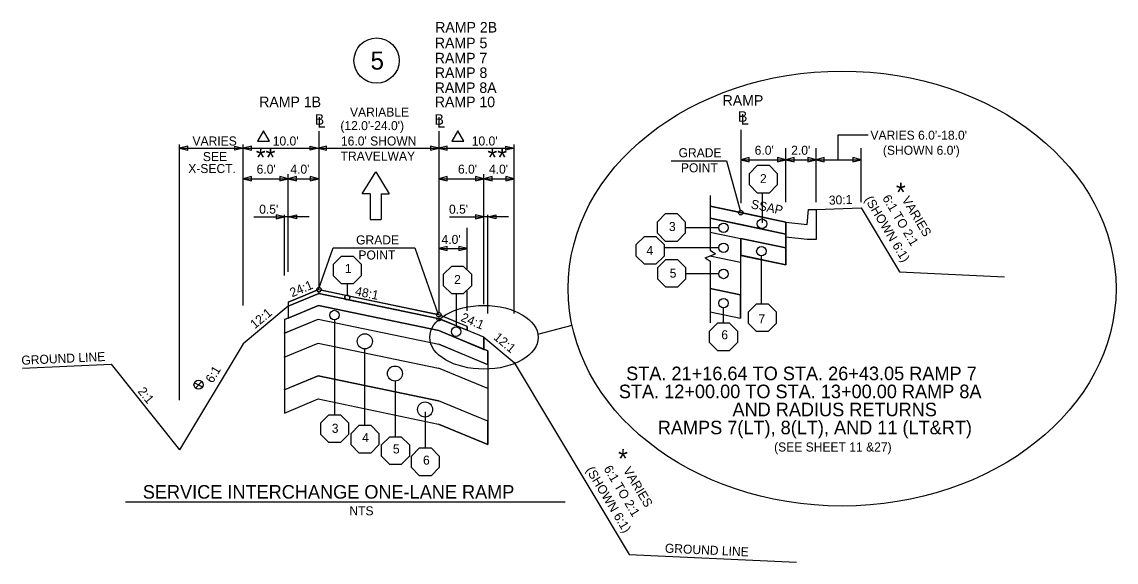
# Model space of a CAD drawing. Extents: x 4649 to 5578, y 4853 to 5383.
# Drawn here: x 4648.7 to 4794, y 5061.2 to 5132.9 of the extents above; entities that cross this region are included whole.
import ezdxf

# ---------------------------------------------------------------- set-up
doc = ezdxf.new("R2010")
doc.units = 0
for name, color, linetype in [('Level 2', 7, 'Continuous'), ('Level 25', 7, 'Continuous'), ('RD_QTY_Stab_Agg_2', 7, 'Continuous'), ('RD_QTY_Sub_Base', 7, 'Continuous'), ('RD_SHT_Bndy', 7, 'Continuous'), ('RD_SHT_Typical', 7, 'Continuous'), ('RD_Sketch1', 7, 'Continuous'), ('RD_Sketch2', 7, 'Continuous'), ('RD_TX_TypSect', 7, 'Continuous'), ('RD_XS_Base', 7, 'Continuous'), ('RD_XS_CurbBase', 7, 'Continuous'), ('RD_XS_CurbFront', 7, 'Continuous'), ('RD_XS_CurbTop', 7, 'Continuous'), ('RD_XS_EarthShd', 7, 'Continuous')]:
    doc.layers.add(name, color=color, linetype=linetype)

msp = doc.modelspace()

# ---------------------------------------------------------------- linework, layer by layer
at = {"layer": 'Level 2'}
for p, q in [((4684.05, 5093.58), (4684.05, 5093.58)), ((4684.05, 5093.53), (4684.05, 5093.53))]:
    msp.add_line(p, q, dxfattribs=at)
at = {"layer": 'Level 25'}
for p, q in [((4740.09, 5108.42), (4750.15, 5106.32)), ((4740.09, 5106.82), (4750.15, 5104.73)), ((4740.09, 5105), (4750.15, 5102.9)), ((4688.07, 5097.35), (4690.01, 5102.88)), ((4690.01, 5102.88), (4700.87, 5102.88)), ((4700.87, 5102.88), (4703.97, 5094.04)), ((4744.14, 5101.9), (4750.15, 5100.65))]:
    msp.add_line(p, q, dxfattribs=at)
msp.add_lwpolyline([(4734.9, 5114.44), (4742.26, 5114.44), (4744.07, 5107.86)], dxfattribs=at)
msp.add_circle((4695.78, 5127.77), 3, dxfattribs=at)
at = {"layer": 'RD_QTY_Stab_Agg_2'}
for p, q in [((4750.15, 5102.9), (4744.15, 5104.15)), ((4744.14, 5101.9), (4750.15, 5100.65))]:
    msp.add_line(p, q, dxfattribs=at)
for points in [[(4744.15, 5104.15), (4744.14, 5101.91), (4744.14, 5101.9)], [(4750.15, 5100.65), (4750.15, 5102.9)]]:
    msp.add_lwpolyline(points, dxfattribs=at)
at = {"layer": 'RD_QTY_Sub_Base'}
for p, q in [((4740.09, 5097.49), (4740.09, 5094.39)), ((4744.13, 5096.65), (4740.09, 5097.49)), ((4744.13, 5093.55), (4744.13, 5096.65)), ((4744.13, 5096.65), (4744.13, 5096.65)), ((4740.09, 5094.39), (4744.13, 5093.55))]:
    msp.add_line(p, q, dxfattribs=at)
at = {"layer": 'RD_SHT_Bndy'}
for p, q in [((4693.86, 5110.08), (4695.68, 5113)), ((4695.68, 5113), (4697.47, 5110.07)), ((4694.95, 5110.08), (4693.86, 5110.08)), ((4694.95, 5110.08), (4694.95, 5106.68)), ((4696.41, 5110.07), (4697.47, 5110.07)), ((4696.41, 5110.07), (4696.41, 5106.67)), ((4694.95, 5106.68), (4696.41, 5106.67))]:
    msp.add_line(p, q, dxfattribs=at)
at = {"layer": 'RD_SHT_Typical'}
for p, q in [((4740.09, 5109.87), (4740.09, 5102.59)), ((4750.15, 5106.32), (4744.15, 5107.57)), ((4754.15, 5107.99), (4760.14, 5108.21)), ((4760.14, 5108.21), (4765.25, 5099.69)), ((4750.15, 5104.73), (4744.13, 5105.97)), ((4750.15, 5106.32), (4750.15, 5100.65)), ((4744.13, 5104.16), (4744.13, 5093.55)), ((4750.15, 5102.9), (4744.15, 5104.15)), ((4750.15, 5102.9), (4750.15, 5100.65)), ((4750.15, 5100.65), (4744.13, 5101.91)), ((4740.09, 5101.11), (4740.09, 5092.95)), ((4685.99, 5096.48), (4688.07, 5097.35)), ((4687.85, 5097.26), (4685.99, 5096.48)), ((4691.73, 5096.59), (4688.43, 5097.27)), ((4684.05, 5095.15), (4688.1, 5096.84)), ((4684.05, 5095.15), (4688.1, 5096.84)), ((4684.05, 5095.67), (4685.99, 5096.48)), ((4685.99, 5096.48), (4684.05, 5095.67)), ((4684.05, 5095.67), (4684.05, 5093.58)), ((4684.05, 5095.67), (4684.05, 5095.15)), ((4688.1, 5096.84), (4691.61, 5096.11)), ((4692.06, 5096.01), (4703.75, 5093.58)), ((4684.05, 5095.15), (4678.05, 5090.15)), ((4683.55, 5093.37), (4688.07, 5095.25)), ((4707.82, 5092.43), (4703.97, 5094.04)), ((4683.52, 5091.55), (4688.04, 5093.43)), ((4683.55, 5093.37), (4683.55, 5080.96)), ((4703.75, 5093.58), (4704.04, 5093.52)), ((4710.04, 5091.02), (4704.04, 5093.52)), ((4704.04, 5093.52), (4704.32, 5093.4)), ((4707.82, 5092.43), (4704.31, 5093.9)), ((4710.54, 5089.2), (4704.02, 5091.91)), ((4707.82, 5092.43), (4707.82, 5091.95)), ((4707.82, 5091.95), (4707.82, 5092.43)), ((4678.05, 5090.15), (4669.61, 5076.09)), ((4683.5, 5088.37), (4688.02, 5090.25)), ((4710.56, 5087.38), (4704.04, 5090.1)), ((4710.04, 5091.02), (4710.04, 5089.4)), ((4710.04, 5091.02), (4714.04, 5087.69)), ((4710.54, 5089.2), (4710.54, 5076.78)), ((4660.53, 5087.45), (4669.61, 5076.09)), ((4710.54, 5084.2), (4704.02, 5086.92)), ((4714.04, 5087.69), (4729.35, 5062.17)), ((4683.5, 5084.04), (4688.02, 5085.92)), ((4683.55, 5080.96), (4688.02, 5082.83)), ((4710.54, 5079.87), (4704, 5082.6)), ((4710.54, 5076.78), (4704, 5079.5))]:
    msp.add_line(p, q, dxfattribs=at)
for points in [[(4740.09, 5108.42), (4744.15, 5107.57)], [(4740.09, 5106.82), (4744.15, 5105.98)], [(4740.09, 5105), (4744.15, 5104.15)], [(4740.04, 5101.83), (4744.13, 5100.98)], [(4688.07, 5097.35), (4703.04, 5094.23), (4703.97, 5094.04)], [(4740.09, 5097.49), (4744.13, 5096.65)], [(4688.1, 5096.84), (4704.04, 5093.52)], [(4703.75, 5094.08), (4703.04, 5094.23), (4692.14, 5096.5)], [(4688.07, 5095.25), (4704.04, 5091.92)], [(4740.09, 5094.39), (4744.13, 5093.55)], [(4688.04, 5093.43), (4704.04, 5090.1)], [(4704.32, 5093.4), (4706.4, 5092.53), (4707.82, 5091.95)], [(4707.82, 5091.95), (4707.82, 5091.95)], [(4688.02, 5090.25), (4704.02, 5086.92)], [(4688.02, 5085.92), (4704.02, 5082.59)], [(4688.02, 5082.83), (4704.02, 5079.49)]]:
    msp.add_lwpolyline(points, dxfattribs=at)
for centre, radius, start, end in [((4688.13, 5097.34), 0.3, 195.3604, 348.2319), ((4691.89, 5096.29), 0.332, 117.6981, 213.838), ((4691.89, 5096.29), 0.332, 302.6258, 38.7657), ((4704.04, 5094.02), 0.3, 168.2319, 334.9662)]:
    msp.add_arc(centre, radius, start, end, dxfattribs=at)
at = {"layer": 'RD_Sketch1'}
for p, q in [((4765.25, 5099.69), (4779.17, 5099.06)), ((4648.74, 5086.91), (4660.53, 5087.45)), ((4729.35, 5062.17), (4751.55, 5061.16))]:
    msp.add_line(p, q, dxfattribs=at)
at = {"layer": 'RD_Sketch2'}
for points in [[(4748.99, 5112.79), (4748.99, 5111.26), (4747.91, 5110.17), (4746.38, 5110.17), (4745.3, 5111.26), (4745.3, 5112.79), (4746.38, 5113.87), (4747.91, 5113.87)], [(4736.78, 5106.37), (4736.78, 5104.84), (4735.7, 5103.76), (4734.17, 5103.76), (4733.09, 5104.84), (4733.09, 5106.37), (4734.17, 5107.45), (4735.7, 5107.45)], [(4733.96, 5103.34), (4733.96, 5101.81), (4732.88, 5100.73), (4731.35, 5100.73), (4730.26, 5101.81), (4730.26, 5103.34), (4731.35, 5104.42), (4732.88, 5104.42)], [(4693.73, 5100.72), (4693.73, 5099.19), (4692.65, 5098.11), (4691.12, 5098.11), (4690.04, 5099.19), (4690.04, 5100.72), (4691.12, 5101.8), (4692.65, 5101.8)], [(4736.81, 5100.27), (4736.81, 5098.74), (4735.73, 5097.66), (4734.2, 5097.66), (4733.12, 5098.74), (4733.12, 5100.27), (4734.2, 5101.36), (4735.73, 5101.36)], [(4708.37, 5099.39), (4708.37, 5097.86), (4707.29, 5096.78), (4705.76, 5096.78), (4704.68, 5097.86), (4704.68, 5099.39), (4705.76, 5100.47), (4707.29, 5100.47)], [(4748.87, 5094.39), (4748.87, 5092.86), (4747.79, 5091.78), (4746.26, 5091.78), (4745.18, 5092.86), (4745.18, 5094.39), (4746.26, 5095.47), (4747.79, 5095.47)], [(4743.71, 5091.84), (4743.71, 5090.31), (4742.63, 5089.23), (4741.1, 5089.23), (4740.02, 5090.31), (4740.02, 5091.84), (4741.1, 5092.92), (4742.63, 5092.92)], [(4692.07, 5079.64), (4692.07, 5078.11), (4690.99, 5077.03), (4689.46, 5077.03), (4688.38, 5078.11), (4688.38, 5079.64), (4689.46, 5080.72), (4690.99, 5080.72)], [(4696.09, 5078.25), (4696.09, 5076.72), (4695, 5075.64), (4693.47, 5075.64), (4692.39, 5076.72), (4692.39, 5078.25), (4693.47, 5079.34), (4695, 5079.34)], [(4700.14, 5076.74), (4700.14, 5075.21), (4699.05, 5074.13), (4697.52, 5074.13), (4696.44, 5075.21), (4696.44, 5076.74), (4697.52, 5077.82), (4699.05, 5077.82)], [(4704.11, 5075.25), (4704.11, 5073.72), (4703.03, 5072.64), (4701.5, 5072.64), (4700.42, 5073.72), (4700.42, 5075.25), (4701.5, 5076.33), (4703.03, 5076.33)]]:
    msp.add_lwpolyline(points, close=True, dxfattribs=at)
at = {"layer": 'RD_TX_TypSect'}
for p, q in [((4688.13, 5118.4), (4688.13, 5097.7)), ((4704.04, 5118.4), (4704.04, 5094.38)), ((4744.15, 5118.55), (4744.15, 5108.83)), ((4761.08, 5117.87), (4757.04, 5117.87)), ((4757.04, 5117.87), (4757.04, 5114.61)), ((4669.61, 5082.66), (4669.61, 5116.61)), ((4669.61, 5116.12), (4678.05, 5116.12)), ((4678.05, 5095.24), (4678.05, 5116.61)), ((4678.05, 5116.12), (4688.05, 5116.12)), ((4688.05, 5116.12), (4704.04, 5116.12)), ((4704.04, 5116.12), (4714.04, 5116.12)), ((4714.04, 5094.16), (4714.04, 5116.61)), ((4750.15, 5108.97), (4750.15, 5116.14)), ((4754.15, 5108.97), (4754.15, 5116.14)), ((4760.14, 5108.97), (4760.14, 5116.14)), ((4744.15, 5114.6), (4750.15, 5114.6)), ((4750.15, 5114.6), (4754.15, 5114.6)), ((4754.15, 5114.6), (4760.14, 5114.6)), ((4678.05, 5112.08), (4684.05, 5112.08)), ((4684.05, 5099.69), (4684.05, 5112.7)), ((4684.05, 5112.08), (4688.05, 5112.08)), ((4704.04, 5112.08), (4710.04, 5112.08)), ((4710.04, 5095.42), (4710.04, 5112.7)), ((4710.04, 5112.08), (4714.04, 5112.08)), ((4747.03, 5106.22), (4747.03, 5110.17)), ((4683.55, 5099.21), (4683.55, 5107.28)), ((4710.54, 5094.16), (4710.54, 5107.28)), ((4679.47, 5107.01), (4683.55, 5107.01)), ((4686.81, 5107.01), (4683.55, 5107.01)), ((4705.45, 5107.01), (4710.04, 5107.01)), ((4713.3, 5107.01), (4710.04, 5107.01)), ((4707.82, 5099.94), (4707.82, 5105.56)), ((4741.24, 5105.56), (4736.83, 5105.56)), ((4704.07, 5102.81), (4707.82, 5102.81)), ((4741.24, 5102.91), (4733.96, 5102.91)), ((4739.42, 5101.59), (4740.78, 5102.1)), ((4739.42, 5101.59), (4740.09, 5101.11)), ((4740.09, 5102.59), (4740.78, 5102.1)), ((4746.89, 5095.51), (4746.89, 5101.82)), ((4741.24, 5099.43), (4736.83, 5099.43)), ((4691.89, 5098.11), (4691.89, 5096.62)), ((4707.82, 5094.55), (4707.82, 5097.31)), ((4706.4, 5092.39), (4706.4, 5096.78)), ((4741.88, 5092.92), (4741.88, 5094.92)), ((4690.22, 5080.72), (4690.22, 5093.36)), ((4717.2, 5091.45), (4721.74, 5092.62)), ((4694.24, 5079.34), (4694.24, 5089.54)), ((4688.02, 5085.92), (4683.55, 5084.06)), ((4698.29, 5077.82), (4698.29, 5085.3)), ((4671.58, 5084.97), (4672.66, 5084.43)), ((4671.71, 5084.28), (4672.53, 5085.12)), ((4683.55, 5084.06), (4683.55, 5080.96)), ((4683.55, 5080.96), (4688.02, 5082.83)), ((4688.02, 5082.83), (4704, 5079.5)), ((4710.54, 5079.87), (4704.02, 5082.59)), ((4702.26, 5076.33), (4702.26, 5081.1)), ((4710.54, 5076.78), (4710.54, 5079.87)), ((4662.44, 5069.15), (4720.81, 5069.15))]:
    msp.add_line(p, q, dxfattribs=at)
for points in [[(4680.77, 5118.46), (4679.97, 5117.07), (4681.57, 5117.07)], [(4706.56, 5118.46), (4705.76, 5117.07), (4707.36, 5117.07)], [(4670.72, 5115.85), (4670.72, 5116.4), (4669.61, 5116.12)], [(4676.95, 5115.85), (4676.95, 5116.4), (4678.05, 5116.12)], [(4679.15, 5115.85), (4679.15, 5116.4), (4678.05, 5116.12)], [(4686.94, 5115.85), (4686.94, 5116.4), (4688.05, 5116.12)], [(4689.15, 5115.85), (4689.15, 5116.4), (4688.05, 5116.12)], [(4702.94, 5116.4), (4702.94, 5115.85), (4704.04, 5116.12)], [(4705.14, 5115.85), (4705.14, 5116.4), (4704.04, 5116.12)], [(4712.93, 5115.85), (4712.93, 5116.4), (4714.04, 5116.12)], [(4745.25, 5114.33), (4745.25, 5114.88), (4744.15, 5114.6)], [(4749.05, 5114.88), (4749.05, 5114.33), (4750.15, 5114.6)], [(4751.25, 5114.33), (4751.25, 5114.88), (4750.15, 5114.6)], [(4753.04, 5114.88), (4753.04, 5114.33), (4754.15, 5114.6)], [(4755.25, 5114.33), (4755.25, 5114.88), (4754.15, 5114.6)], [(4759.04, 5114.88), (4759.04, 5114.33), (4760.14, 5114.6)], [(4679.15, 5111.81), (4679.15, 5112.36), (4678.05, 5112.08)], [(4682.95, 5112.36), (4682.95, 5111.81), (4684.05, 5112.08)], [(4685.15, 5111.81), (4685.15, 5112.36), (4684.05, 5112.08)], [(4686.94, 5112.36), (4686.94, 5111.81), (4688.05, 5112.08)], [(4705.14, 5111.81), (4705.14, 5112.36), (4704.04, 5112.08)], [(4708.94, 5112.36), (4708.94, 5111.81), (4710.04, 5112.08)], [(4711.14, 5111.81), (4711.14, 5112.36), (4710.04, 5112.08)], [(4712.93, 5112.36), (4712.93, 5111.81), (4714.04, 5112.08)], [(4682.45, 5107.28), (4682.45, 5106.73), (4683.55, 5107.01)], [(4685.15, 5107.28), (4685.15, 5106.73), (4684.05, 5107.01)], [(4708.94, 5107.28), (4708.94, 5106.73), (4710.04, 5107.01)], [(4711.64, 5107.28), (4711.64, 5106.73), (4710.54, 5107.01)], [(4705.17, 5102.53), (4705.17, 5103.08), (4704.07, 5102.81)], [(4706.71, 5103.08), (4706.71, 5102.53), (4707.82, 5102.81)]]:
    msp.add_lwpolyline(points, close=True, dxfattribs=at)
for points in [[(4704.02, 5082.59), (4704, 5082.59), (4688.02, 5085.92)], [(4704, 5079.5), (4704, 5079.5)], [(4704, 5079.5), (4704.02, 5079.49), (4710.54, 5076.78)]]:
    msp.add_lwpolyline(points, dxfattribs=at)
for centre, radius in [((4744.15, 5107.57), 0.3), ((4741.87, 5105.56), 0.63), ((4746.97, 5106.1), 0.63), ((4741.87, 5102.91), 0.63), ((4746.89, 5102.45), 0.63), ((4741.87, 5099.43), 0.63), ((4688.13, 5097.34), 0.3), ((4691.89, 5096.29), 0.332), ((4741.87, 5095.55), 0.63), ((4690.19, 5093.97), 0.63), ((4704.04, 5094.02), 0.3), ((4694.22, 5090.48), 1), ((4706.34, 5091.77), 0.63), ((4698.22, 5086.2), 1), ((4672.13, 5084.71), 0.6), ((4702.22, 5081.43), 1), ((4702.22, 5081.43), 1)]:
    msp.add_circle(centre, radius, dxfattribs=at)
for centre, major_axis, ratio in [((4757.61, 5097.49), (-36.39, 0), 0.793631), ((4710.04, 5091.02), (-7.2, 0), 0.587586)]:
    msp.add_ellipse(centre, major_axis=major_axis, ratio=ratio, dxfattribs=at)
at = {"layer": 'RD_XS_Base'}
for p, q in [((4744.15, 5107.57), (4740.09, 5108.42)), ((4740.09, 5108.42), (4740.09, 5106.82)), ((4750.15, 5106.32), (4744.15, 5107.57)), ((4740.09, 5106.82), (4744.15, 5105.98)), ((4744.15, 5105.98), (4750.15, 5104.73)), ((4750.15, 5104.73), (4750.15, 5106.32)), ((4688.1, 5096.84), (4684.05, 5095.15)), ((4703.75, 5093.58), (4688.1, 5096.84)), ((4684.05, 5093.58), (4688.07, 5095.25)), ((4684.05, 5095.15), (4684.05, 5093.58)), ((4688.07, 5095.25), (4704.04, 5091.92)), ((4704.04, 5091.92), (4710.04, 5089.41)), ((4710.04, 5089.41), (4710.04, 5091.02))]:
    msp.add_line(p, q, dxfattribs=at)
msp.add_lwpolyline([(4710.04, 5091.02), (4706.4, 5092.53), (4704.32, 5093.4)], dxfattribs=at)
msp.add_circle((4706.34, 5091.77), 0.63, dxfattribs=at)
msp.add_arc((4704.04, 5093.52), 0.3, 168.2319, 337.3801, dxfattribs=at)
at = {"layer": 'RD_XS_CurbBase'}
for p, q in [((4754.15, 5107.99), (4754.15, 5103.99)), ((4752.98, 5103.99), (4750.15, 5104.32)), ((4754.15, 5103.99), (4752.98, 5103.99))]:
    msp.add_line(p, q, dxfattribs=at)
at = {"layer": 'RD_XS_CurbFront'}
msp.add_line((4750.15, 5106.32), (4750.15, 5104.83), dxfattribs=at)
at = {"layer": 'RD_XS_CurbTop'}
for p, q in [((4752.98, 5105.99), (4753.15, 5107.99)), ((4753.15, 5107.99), (4754.15, 5107.99)), ((4750.15, 5106.32), (4752.98, 5105.99))]:
    msp.add_line(p, q, dxfattribs=at)
at = {"layer": 'RD_XS_EarthShd'}
for p, q in [((4740.09, 5106.82), (4740.09, 5105)), ((4744.15, 5105.98), (4740.09, 5106.82)), ((4750.15, 5104.73), (4744.15, 5105.98)), ((4740.09, 5105), (4744.15, 5104.15)), ((4744.15, 5104.15), (4750.15, 5102.9)), ((4750.15, 5103.46), (4750.15, 5104.73)), ((4750.15, 5102.9), (4750.15, 5104.56)), ((4750.15, 5104.56), (4750.15, 5103.46)), ((4704.04, 5091.92), (4688.07, 5095.25)), ((4683.55, 5091.56), (4688.04, 5093.43)), ((4683.55, 5093.37), (4683.55, 5091.56)), ((4688.04, 5093.43), (4704.04, 5090.1)), ((4710.04, 5089.4), (4704.04, 5091.92)), ((4704.04, 5090.1), (4710.54, 5087.39)), ((4710.54, 5089.2), (4710.04, 5089.41)), ((4710.54, 5087.39), (4710.54, 5089.2))]:
    msp.add_line(p, q, dxfattribs=at)
for points in [[(4688.07, 5095.25), (4684.05, 5093.58), (4683.55, 5093.37)], [(4710.04, 5089.41), (4710.04, 5089.4)]]:
    msp.add_lwpolyline(points, dxfattribs=at)

# ---------------------------------------------------------------- texts
at = {"layer": 'Level 25'}
for s, height, p in [('5', 2.4, (4694.98, 5126.57)), ('RAMP', 1.4, (4741.74, 5121.78)), ('B ', 1.4, (4743.78, 5119.64)), ('GRADE', 1.2, (4735.89, 5114.93)), ('POINT', 1.2, (4736.2, 5112.93))]:
    msp.add_text(s, height=height, dxfattribs=at).set_placement(p)
for s, rotation, p in [('SSAP', 348.2319, (4745.42, 5108.16)), ('30:1', 2.069, (4755.87, 5108.62))]:
    msp.add_text(s, height=1.2, rotation=rotation, dxfattribs=at).set_placement(p)
at = {"layer": 'RD_TX_TypSect'}
for s, height, p in [('RAMP 2B', 1.4, (4703.57, 5131.49)), ('RAMP 5', 1.4, (4703.52, 5129.41)), ('RAMP 7', 1.4, (4703.51, 5127.4)), ('RAMP 8', 1.4, (4703.52, 5125.46)), ('RAMP 8A', 1.4, (4703.5, 5123.47)), ('RAMP 1B', 1.4, (4680.19, 5121.58)), ('RAMP 10', 1.4, (4703.51, 5121.58)), ('B', 1.4, (4687.57, 5119.25)), ('L', 1.4, (4687.94, 5118.86)), ('B', 1.4, (4703.47, 5119.25)), ('L', 1.4, (4703.84, 5118.86)), ('L', 1.4, (4744.17, 5119.26)), ('VARIES', 1.2, (4671.33, 5116.49)), ("10.0'", 1.2, (4681.99, 5116.49)), ("16.0' SHOWN", 1.2, (4691.05, 5116.49)), ("10.0'", 1.2, (4708.42, 5116.49)), ("VARIES 6.0'-18.0'", 1.2, (4761.37, 5117.26)), ('**', 2.5, (4679.74, 5113.66)), ('**', 2.5, (4710.51, 5113.66)), ("6.0'", 1.2, (4746, 5115.26)), ("2.0'", 1.2, (4750.85, 5115.26)), ("(SHOWN 6.0')", 1.2, (4763.03, 5115.26)), ('SEE', 1.2, (4672.71, 5114.42)), ('TRAVELWAY', 1.2, (4691, 5114.49)), ('X-SECT.', 1.2, (4670.77, 5112.83)), ("6.0'", 1.2, (4679.85, 5112.75)), ("4.0'", 1.2, (4684.33, 5112.75)), ("6.0'", 1.2, (4706.59, 5112.75)), ("4.0'", 1.2, (4710.71, 5112.75)), ('2', 1.2, (4746.7, 5111.49)), ('*', 2.5, (4764.76, 5109.04)), ("0.5'", 1.2, (4680.19, 5107.43)), ("0.5'", 1.2, (4705.4, 5107.43)), ('3', 1.2, (4734.61, 5105.13)), ('GRADE', 1.2, (4693.06, 5103.35)), ("4.0'", 1.2, (4704.41, 5103.42)), ('4', 1.2, (4731.63, 5101.96)), ('POINT', 1.2, (4693.37, 5101.35)), ('1', 1.2, (4691.57, 5099.55)), ('5', 1.2, (4734.71, 5098.94)), ('2', 1.2, (4706.08, 5098.09)), ('7', 1.2, (4746.5, 5092.88)), ('6', 1.2, (4741.57, 5090.75)), ('STA. 21+16.64 TO STA. 26+43.05 RAMP 7', 1.8, (4728.93, 5085.32)), ('STA. 12+00.00 TO STA. 13+00.00 RAMP 8A', 1.8, (4727.96, 5082.93)), ('AND RADIUS RETURNS', 1.8, (4743.05, 5080.53)), ('3', 1.2, (4689.83, 5078.33)), ('RAMPS 7(LT), 8(LT), AND 11 (LT&RT)', 1.8, (4733.13, 5078.14)), ('4', 1.2, (4693.87, 5077.1)), ('5', 1.2, (4697.95, 5075.59)), ('(SEE SHEET 11 &27)', 1.2, (4748.58, 5075.85)), ('6', 1.2, (4701.95, 5074.1)), ('*', 2.5, (4727.86, 5073.67)), ('SERVICE INTERCHANGE ONE-LANE RAMP', 1.8, (4664.73, 5069.59)), ('NTS', 1.2, (4692.17, 5067.37))]:
    msp.add_text(s, height=height, dxfattribs=at).set_placement(p)
for s, rotation, p in [('VARIABLE', 0.0016, (4692.25, 5120.33)), ("(12.0'-24.0')", 0.0016, (4690.97, 5118.53)), ('(SHOWN 6:1)', 300.9638, (4760.56, 5109.35)), ('6:1 TO 2:1', 300.9638, (4762.91, 5109.51)), ('VARIES', 300.9638, (4765.49, 5109.3)), ('24:1', 22.619, (4684.56, 5096.32)), ('48:1', 348.2317, (4692.86, 5096.61)), ('12:1', 39.8056, (4679.61, 5092.08)), ('24:1', 337.3801, (4706.87, 5093.22)), ('12:1', 320.1939, (4711.23, 5090.85)), ('GROUND LINE', 2.6095, (4648.63, 5087.36)), ('6:1', 59.0362, (4674, 5084.84)), ('2:1', 308.6598, (4663.99, 5083.82)), ('(SHOWN 6:1)', 300.9638, (4723.54, 5073.41)), ('6:1 TO 2:1', 300.9638, (4725.9, 5073.57)), ('VARIES', 300.9638, (4728.47, 5073.36)), ('GROUND LINE', 357.3905, (4734.05, 5062.42))]:
    msp.add_text(s, height=1.2, rotation=rotation, dxfattribs=at).set_placement(p)

doc.saveas('drawing.dxf')
